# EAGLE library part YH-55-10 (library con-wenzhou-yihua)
RJ11 6 connects Source: YH-55-10.pdf
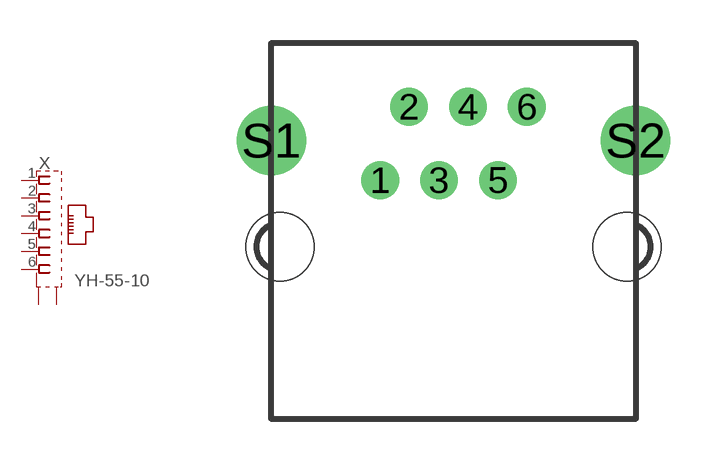
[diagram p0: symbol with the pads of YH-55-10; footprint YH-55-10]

Designator prefix X

## YH-55-10 (OC_FARNELL: unknown; OC_NEWARK: unknown)  [YH-55-10]
1  1  pas
2  2  pas
3  3  pas
4  4  pas
5  5  pas
6  6  pas
S1  S  pas
S2  S  pas

## Footprint YH-55-10 (pad centres in mm)
RJ11 6 connects Source: YH-55-10.pdf
drill 0.8 pad 1.3 round: 1 -2.54,2.3; 2 -1.54,4.84; 3 -0.5,2.3; 4 0.5,4.84; 5 1.54,2.3; 6 2.54,4.84
drill 1.6 pad 2.184 round: S1 -6.3,3.68; S2 6.3,3.68
hole 2.36 at -6,0
hole 2.36 at 6,0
